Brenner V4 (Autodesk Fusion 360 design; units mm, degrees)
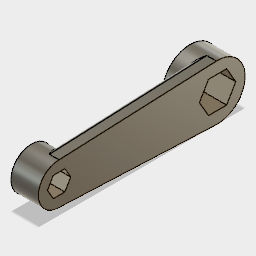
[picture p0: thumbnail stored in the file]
sketch "Sketch1" plane through (0, 0, 0) normal (1, 0, 0) x axis (0, 0, -1)
  line L1 (12.7017, 0) -> (6.3509, -11)
  line L2 (6.3509, 11) -> (12.7017, 0)
  line L3 (-6.3509, 11) -> (6.3509, 11)
  line L4 (-12.7017, 0) -> (-6.3509, 11)
  line L5 (-6.3509, -11) -> (-12.7017, 0)
  line L6 (6.3509, -11) -> (-6.3509, -11)
  line L7 (-130, 25) -> (20, 25)
  line L8 (-106.9171, 0) -> (-110.9585, -7)
  line L9 (-110.9585, 7) -> (-106.9171, 0)
  line L10 (-119.0415, 7) -> (-110.9585, 7)
  line L11 (-123.0829, 0) -> (-119.0415, 7)
  line L12 (-119.0415, -7) -> (-123.0829, 0)
  line L13 (-110.9585, -7) -> (-119.0415, -7)
  circle C1 centre (0, 0) radius 20
  circle C2 centre (-115, 0) radius 15
  point P10 (20, 25)
  point P11 (-130, 25)
  dimension "d1" distance P10 P11 = 150
extrude "Extrude1" sketch "Sketch1" profile of L1 L2 L3 L4 L5 L6 C1 L8 L9 L10 L11 L12 L13 C2 blind 20
sketch "Sketch2" plane through (20, 0, 0) normal (1, 0, 0) x axis (0, 0, -1)
  line L1 (-6.3509, -11) -> (6.3509, -11)
  line L2 (-12.7017, 0) -> (-6.3509, -11)
  line L3 (-6.3509, 11) -> (-12.7017, 0)
  line L4 (6.3509, 11) -> (-6.3509, 11)
  line L5 (12.7017, 0) -> (6.3509, 11)
  line L6 (6.3509, -11) -> (12.7017, 0)
  line L7 (-0.872, 19.981) -> (-115.0001, 15)
  line L8 (-0.872, -19.981) -> (-115.0001, -15)
  circle C1 centre (0, 0) radius 20
  circle C2 centre (-115, 0) radius 15
extrude "Extrude2" sketch "Sketch2" profile of C1 C2 L7 L8 blind -10
fillet "Fillet1" radius 3
sketch "Sketch3" plane through (20, 0, 0) normal (1, 0, 0) x axis (0, 0, -1)
  line L1 (-6.3509, -11) -> (6.3509, -11)
  line L2 (-12.7017, 0) -> (-6.3509, -11)
  line L3 (-6.3509, 11) -> (-12.7017, 0)
  line L4 (6.3509, 11) -> (-6.3509, 11)
  line L5 (12.7017, 0) -> (6.3509, 11)
  line L6 (6.3509, -11) -> (12.7017, 0)
  line L7 (-119.0415, -7) -> (-110.9585, -7)
  line L8 (-123.0829, 0) -> (-119.0415, -7)
  line L9 (-119.0415, 7) -> (-123.0829, 0)
  line L10 (-110.9585, 7) -> (-119.0415, 7)
  line L11 (-106.9171, 0) -> (-110.9585, 7)
  line L12 (-110.9585, -7) -> (-106.9171, 0)
  line L13 (-0.872, -19.981) -> (-115.0001, -15)
  line L14 (-115.0001, 15) -> (-0.872, 19.981)
  line L15 (-106.5707, 0) -> (-110.7853, -7.3)
  line L16 (-110.7853, 7.3) -> (-106.5707, 0)
  line L17 (-119.2147, 7.3) -> (-110.7853, 7.3)
  line L18 (-123.4293, 0) -> (-119.2147, 7.3)
  line L19 (-119.2147, -7.3) -> (-123.4293, 0)
  line L20 (-110.7853, -7.3) -> (-119.2147, -7.3)
  line L21 (13.0481, 0) -> (6.5241, -11.3)
  line L22 (6.5241, 11.3) -> (13.0481, 0)
  line L23 (-6.5241, 11.3) -> (6.5241, 11.3)
  line L24 (-13.0481, 0) -> (-6.5241, 11.3)
  line L25 (-6.5241, -11.3) -> (-13.0481, 0)
  line L26 (6.5241, -11.3) -> (-6.5241, -11.3)
  arc A1 centre (-115, 0) radius 15 clockwise from (-115.0001, -15) to (-115.0001, 15)
  arc A2 centre (0, 0) radius 20 clockwise from (-0.872, 19.981) to (-0.872, -19.981)
extrude "Extrude3" sketch "Sketch3" profile of L1 L2 L3 L4 L5 L6 L7 L8 L9 L10 L11 L12 L15 L16 L17 L18 L19 L20 blind -42
sketch "Sketch4" plane through (20, 0, 0) normal (1, 0, 0) x axis (0, 0, -1)
  line L1 (-110.7853, -7.3) -> (-106.5707, 0)
  line L2 (-119.2147, -7.3) -> (-110.7853, -7.3)
  line L3 (-123.4293, 0) -> (-119.2147, -7.3)
  line L4 (-119.2147, 7.3) -> (-123.4293, 0)
  line L5 (-110.7853, 7.3) -> (-119.2147, 7.3)
  line L6 (-106.5707, 0) -> (-110.7853, 7.3)
  line L7 (-6.3509, -11) -> (6.3509, -11)
  line L8 (-12.7017, 0) -> (-6.3509, -11)
  line L9 (-6.3509, 11) -> (-12.7017, 0)
  line L10 (6.3509, 11) -> (-6.3509, 11)
  line L11 (12.7017, 0) -> (6.3509, 11)
  line L12 (6.3509, -11) -> (12.7017, 0)
  line L13 (-0.872, -19.981) -> (-115.0001, -15)
  line L14 (-115.0001, 15) -> (-0.872, 19.981)
  line L15 (13.1636, 0) -> (6.5818, -11.4)
  line L16 (6.5818, 11.4) -> (13.1636, 0)
  line L17 (-6.5818, 11.4) -> (6.5818, 11.4)
  line L18 (-13.1636, 0) -> (-6.5818, 11.4)
  line L19 (-6.5818, -11.4) -> (-13.1636, 0)
  line L20 (6.5818, -11.4) -> (-6.5818, -11.4)
  arc A1 centre (-115, 0) radius 15 clockwise from (-115.0001, -15) to (-115.0001, 15)
  arc A2 centre (0, 0) radius 20 clockwise from (-0.872, 19.981) to (-0.872, -19.981)
extrude "Extrude4" sketch "Sketch4" profile of L7 L8 L9 L10 L11 L12 L15 L16 L17 L18 L19 L20 blind -50
sketch "Sketch5" plane through (20, 0, 0) normal (1, 0, 0) x axis (0, 0, -1)
  line L1 (6.5818, -11.4) -> (13.1636, 0)
  line L2 (-6.5818, -11.4) -> (6.5818, -11.4)
  line L3 (-13.1636, 0) -> (-6.5818, -11.4)
  line L4 (-6.5818, 11.4) -> (-13.1636, 0)
  line L5 (6.5818, 11.4) -> (-6.5818, 11.4)
  line L6 (13.1636, 0) -> (6.5818, 11.4)
  line L7 (-110.7853, -7.3) -> (-106.5707, 0)
  line L8 (-119.2147, -7.3) -> (-110.7853, -7.3)
  line L9 (-123.4293, 0) -> (-119.2147, -7.3)
  line L10 (-119.2147, 7.3) -> (-123.4293, 0)
  line L11 (-110.7853, 7.3) -> (-119.2147, 7.3)
  line L12 (-106.5707, 0) -> (-110.7853, 7.3)
  line L13 (-0.872, -19.981) -> (-115.0001, -15)
  line L14 (-115.0001, 15) -> (-0.872, 19.981)
  arc A1 centre (-115, 0) radius 15 clockwise from (-115.0001, -15) to (-115.0001, 15)
  arc A2 centre (0, 0) radius 20 clockwise from (-0.872, 19.981) to (-0.872, -19.981)
sketch "Sketch6" plane through (10, 0, 0) normal (-1, 0, 0) x axis (0, 0, 1)
  line L1 (106.5122, -12.3676) -> (11.2669, -16.5245)
  line L2 (11.2669, 16.5245) -> (106.5122, 12.3676)
  curve K1 (94.9769, -4.4555) -> (25.1312, -4.4555)
  curve K2 (94.9769, 6.5445) -> (94.9769, -4.4555)
  curve K3 (25.1312, 6.5445) -> (94.9769, 6.5445)
  curve K4 (25.1312, -4.4555) -> (25.1312, 6.5445)
  arc A1 centre (115, 0) radius 15 clockwise from (106.5122, -12.3676) to (106.5122, 12.3676)
  arc A2 centre (0, 0) radius 20 clockwise from (11.2669, 16.5245) to (11.2669, -16.5245)
extrude "Extrude5" sketch "Sketch6" blind -1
